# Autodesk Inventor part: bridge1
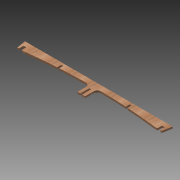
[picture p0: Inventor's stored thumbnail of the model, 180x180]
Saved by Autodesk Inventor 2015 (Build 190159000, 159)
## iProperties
Created: 2015-04
Part Number: bridge1
Material: Wood (Birch)
Document SubType Name: Modeling
Designer: sungeun
Density: 0.55 g/cm^3
Appearance: Birch - Natural Polished
Author: sungeun
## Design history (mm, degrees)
sketch "Sketch1"
  geometry: L1 (-948.841, 0)-(-970, 120); L2 (-970, 120)-(0, 120); L3 (0, 120)-(0, 120); L4 (970, 120)-(0, 120); L5 (948.841, 0)-(970, 120); L6 (-948.841, 0)-(-848.841, 0); L7 (948.841, 0)-(848.841, 0); L8 (50, 120)-(-50, 120); L9 (-50, 51.479)-(-50, -110); L10 (-50, -110)-(50, -110); L11 (50, -110)-(50, 51.479); A1 r 7000 centre (0, -6948.343) between (848.841, 0) and (50, 51.479); A2 r 7000 centre (0, -6948.343) between (-50, 51.479) and (-848.841, 0); 2 further points
  constraints: 22 end point, 4 horizontal, 4 point on circle, 2 centre point, 2 parallel, 2 symmetric about line, 2 vertical alignment, 1 horizontal alignment, 1 midpoint, 1 perpendicular, 1 point on line, 1 vertical
  dimensions: "depth" = 970 distance of L1.end L2.end; "height" = 120 distance from line of point (0, 0) L2; "d2" = 80 deg angle of L2 L1; "d22" = 100 distance of L1.start L6.end; "d23" = 100 distance of L7.end L5.start; "d26" = 230 distance of L8.end L9.end; "d27" = 100 distance of L9.end L10.end
extrude "Extrusion1" new body sketch "Sketch1" distance "d6" = 24 (= 2 x thickness); taper "d7" = 0 deg
sketch "Sketch2"
  geometry: L1 (-927.445, 60)-(-891.445, 60); L2 (-891.445, 60)-(-891.445, 0); L3 (-891.445, 0)-(-927.445, 0); L4 (-927.445, 0)-(-927.445, 60); L5 (-859.445, 0)-(-948.841, 0) reference; L6 (0, 230)-(0, 0); L7 (927.445, 60)-(891.445, 60); L8 (891.445, 60)-(891.445, 0); L9 (927.445, 0)-(927.445, 60); L10 (891.445, 0)-(927.445, 0); L11 (-848.841, 0)-(-948.841, 0) reference; 4 further points
  constraints: 18 end point, 4 symmetric about line, 2 midpoint, 2 parallel, 1 coincident, 1 horizontal, 1 perpendicular, 1 point on line, 1 vertical
  dimensions: "d8" = 60 distance of L1.end L2.end; "d9" = 36 distance of L2.end L3.end (= 3 x thickness); "d10" = 0 distance between parallel lines of L5 L3; "d25" = 909.445 distance of L6.end point (-909.445, 0)
extrude "Extrusion2" cut sketch "Sketch2" stored distance "d11" = 0; taper "d12" = 0 deg
sketch "Sketch3"
  geometry: L1 (-12, 10)-(12, 10); L2 (12, 10)-(12, -110); L3 (12, -110)-(-12, -110); L4 (-12, -110)-(-12, 10); L5 (-462, 90)-(-438, 90); L6 (-438, 90)-(-438, -30); L7 (-438, -30)-(-462, -30); L8 (-462, -30)-(-462, 90); L9 (0, 10)-(0, -110); L10 (462, 90)-(438, 90); L11 (438, 90)-(438, -30); L12 (438, -30)-(462, -30); L13 (462, -30)-(462, 90); L14 (970, 120)-(-970, 120) reference; 5 further points
  constraints: 26 end point, 5 parallel, 5 symmetric about line, 3 midpoint, 2 horizontal, 2 perpendicular, 1 vertical alignment
  dimensions: "d13" = 120 distance of L1.end L2.end; "d14" = 24 distance of L2.end L3.end (= 2 x thickness); "d15" = 120 distance of L5.end L6.end (= d13); "d16" = 24 distance of L6.end L7.end (= d14); "d21" = 30 distance between parallel lines of L14 L5; "d29" = 900 diameter of point (-450, -30) L9; "d30" = 110 distance between parallel lines of L1 L14
extrude "Extrusion3" cut sketch "Sketch3" stored distance "d18" = 10; taper "d19" = 0 deg
fillet "Fillet1" dims "d28" = 50
body "Solid1"
other parameters: "thickness" = 12 [user parameter; used in 3 equation terms]
